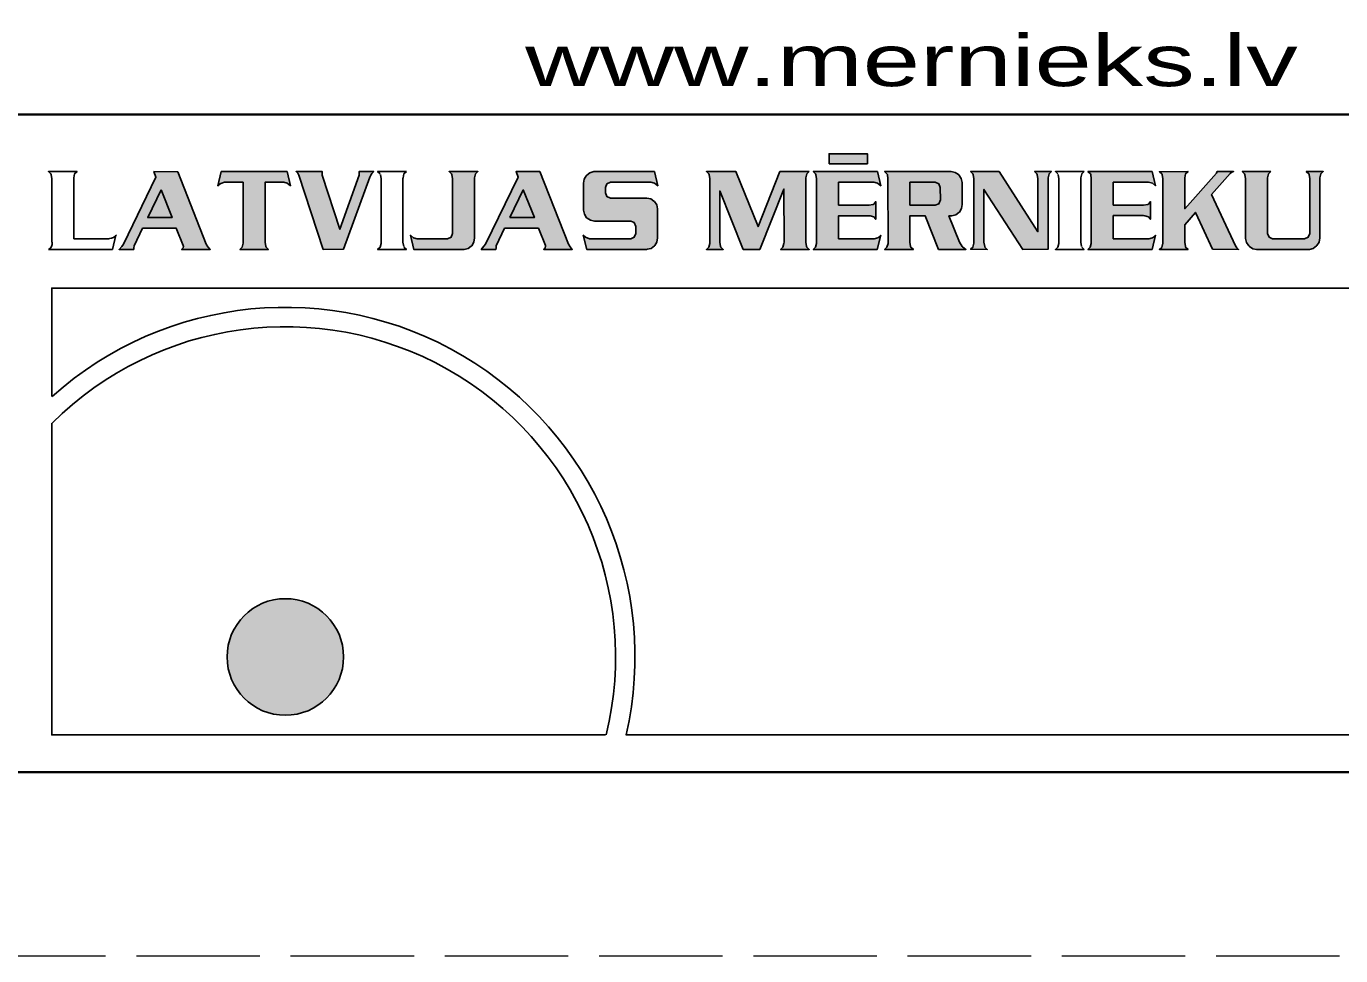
# Model space of a CAD drawing. Extents: x 380758 to 381729, y 283236 to 283533.
# Drawn here: x 381701.8 to 381719.69, y 283235.88 to 283248.53 of the extents above; entities that cross this region are included whole.
import ezdxf

# ---------------------------------------------------------------- set-up
doc = ezdxf.new("R2010")
doc.units = 0
doc.header["$LTSCALE"] = 0.28
doc.linetypes.add('LONG_DASHED', pattern=[7.5, 6, -1.5])
doc.layers.add('63', color=7, linetype='Continuous', lineweight=13)

msp = doc.modelspace()

# ---------------------------------------------------------------- hatches: boundary and pattern name
at = {"layer": '63'}
for points in [[(381712.727, 283246.655), (381713.248, 283246.655), (381713.248, 283246.791), (381712.726, 283246.791)], [(381703.858, 283246.547), (381703.533, 283246.548), (381703.561, 283246.475), (381703.118, 283245.561), (381703.096, 283245.531), (381703.06, 283245.489), (381703.26, 283245.49), (381703.262, 283245.511), (381703.263, 283245.538), (381703.379, 283245.778), (381703.839, 283245.777), (381703.933, 283245.541), (381703.935, 283245.529), (381703.931, 283245.512), (381703.91, 283245.49), (381704.3, 283245.489), (381704.269, 283245.524), (381704.247, 283245.562)], [(381704.749, 283246.403), (381704.749, 283245.586), (381704.749, 283245.573), (381704.735, 283245.518), (381704.704, 283245.49), (381705.093, 283245.49), (381705.061, 283245.518), (381705.057, 283245.528), (381705.048, 283245.586), (381705.047, 283246.403), (381705.301, 283246.403), (381705.047, 283246.403), (381705.301, 283246.403), (381705.348, 283246.389), (381705.392, 283246.355), (381705.346, 283246.548), (381704.45, 283246.549), (381704.404, 283246.355), (381704.435, 283246.381), (381704.446, 283246.388), (381704.497, 283246.403)], [(381705.837, 283245.49), (381706.113, 283245.491), (381706.474, 283246.473), (381706.487, 283246.502), (381706.499, 283246.525), (381706.526, 283246.548), (381706.328, 283246.548), (381706.328, 283246.502), (381706.066, 283245.764), (381705.825, 283246.499), (381705.825, 283246.548), (381705.47, 283246.548), (381705.493, 283246.529), (381705.509, 283246.499)], [(381707.758, 283245.489), (381707.811, 283245.502), (381707.854, 283245.535), (381707.86, 283245.54), (381707.889, 283245.589), (381707.898, 283245.645), (381707.898, 283246.452), (381707.899, 283246.466), (381707.913, 283246.52), (381707.944, 283246.548), (381707.553, 283246.548), (381707.587, 283246.519), (381707.591, 283246.51), (381707.599, 283246.451), (381707.599, 283245.706), (381707.58, 283245.654), (381707.58, 283245.654), (381707.531, 283245.633), (381707.118, 283245.633), (381707.07, 283245.648), (381707.025, 283245.682), (381707.072, 283245.489), (381707.75, 283245.489)], [(381708.788, 283246.549), (381708.464, 283246.549), (381708.491, 283246.475), (381708.049, 283245.561), (381708.026, 283245.532), (381707.99, 283245.489), (381708.191, 283245.489), (381708.192, 283245.511), (381708.195, 283245.538), (381708.309, 283245.777), (381708.769, 283245.777), (381708.864, 283245.541), (381708.866, 283245.529), (381708.861, 283245.512), (381708.841, 283245.489), (381709.23, 283245.489), (381709.2, 283245.524), (381709.177, 283245.562)], [(381710.074, 283245.855), (381710.095, 283245.803), (381710.093, 283245.707), (381710.093, 283245.707), (381710.074, 283245.655), (381710.025, 283245.634), (381709.473, 283245.634), (381709.463, 283245.635), (381709.411, 283245.657), (381709.38, 283245.682), (381709.426, 283245.49), (381710.243, 283245.49), (381710.251, 283245.491), (381710.304, 283245.502), (381710.348, 283245.536), (381710.354, 283245.542), (381710.382, 283245.59), (381710.392, 283245.645), (381710.392, 283246.03), (381710.392, 283246.04), (381710.379, 283246.095), (381710.348, 283246.141), (381710.341, 283246.148), (381710.297, 283246.178), (381710.243, 283246.188), (381709.749, 283246.187), (381709.701, 283246.208), (381709.681, 283246.259), (381709.682, 283246.332), (381709.701, 283246.382), (381709.749, 283246.403), (381710.301, 283246.403), (381710.349, 283246.39), (381710.394, 283246.355), (381710.348, 283246.548), (381709.532, 283246.548), (381709.524, 283246.548), (381709.47, 283246.534), (381709.426, 283246.502), (381709.419, 283246.493), (381709.391, 283246.446), (381709.383, 283246.39), (381709.382, 283246.032), (381709.381, 283246.023), (381709.394, 283245.967), (381709.425, 283245.921), (381709.432, 283245.914), (381709.478, 283245.886), (381709.533, 283245.875), (381710.025, 283245.875)], [(381712.456, 283246.548), (381712.056, 283246.548), (381711.758, 283245.801), (381711.458, 283246.548), (381711.055, 283246.548), (381711.087, 283246.519), (381711.091, 283246.51), (381711.1, 283246.451), (381711.1, 283245.586), (381711.1, 283245.572), (381711.087, 283245.518), (381711.055, 283245.49), (381711.284, 283245.49), (381711.252, 283245.519), (381711.248, 283245.528), (381711.238, 283245.586), (381711.238, 283246.286), (381711.557, 283245.49), (381711.781, 283245.49), (381712.111, 283246.311), (381712.112, 283245.586), (381712.111, 283245.572), (381712.098, 283245.518), (381712.065, 283245.49), (381712.456, 283245.49), (381712.423, 283245.519), (381712.42, 283245.528), (381712.411, 283245.586), (381712.41, 283246.452), (381712.411, 283246.465), (381712.423, 283246.52)], [(381712.556, 283246.452), (381712.556, 283245.586), (381712.556, 283245.572), (381712.543, 283245.518), (381712.51, 283245.49), (381713.382, 283245.49), (381713.429, 283245.682), (381713.402, 283245.658), (381713.388, 283245.649), (381713.338, 283245.634), (381712.855, 283245.634), (381712.855, 283245.948), (381713.269, 283245.948), (381713.283, 283245.947), (381713.334, 283245.934), (381713.36, 283245.899), (381713.36, 283246.14), (381713.334, 283246.106), (381713.325, 283246.101), (381713.269, 283246.091), (381712.855, 283246.092), (381712.856, 283246.403), (381713.337, 283246.403), (381713.387, 283246.389), (381713.43, 283246.355), (381713.383, 283246.548), (381712.51, 283246.549), (381712.543, 283246.519), (381712.547, 283246.51)], [(381713.527, 283246.451), (381713.528, 283245.586), (381713.528, 283245.572), (381713.514, 283245.518), (381713.482, 283245.49), (381713.873, 283245.49), (381713.84, 283245.519), (381713.836, 283245.528), (381713.827, 283245.586), (381713.827, 283245.948), (381714.033, 283245.948), (381714.216, 283245.49), (381714.588, 283245.49), (381714.586, 283245.49), (381714.542, 283245.525), (381714.537, 283245.53), (381714.503, 283245.586), (381714.358, 283245.948), (381714.389, 283245.948), (381714.398, 283245.948), (381714.449, 283245.96), (381714.494, 283245.992), (381714.5, 283245.998), (381714.528, 283246.045), (381714.539, 283246.102), (381714.538, 283246.389), (381714.539, 283246.401), (381714.524, 283246.455), (381714.494, 283246.503), (381714.489, 283246.508), (381714.442, 283246.538), (381714.389, 283246.548), (381713.482, 283246.548), (381713.514, 283246.519), (381713.519, 283246.511)], [(381715.041, 283246.548), (381714.651, 283246.548), (381714.683, 283246.52), (381714.687, 283246.51), (381714.696, 283246.451), (381714.696, 283245.586), (381714.696, 283245.573), (381714.683, 283245.518), (381714.651, 283245.491), (381714.88, 283245.49), (381714.848, 283245.518), (381714.844, 283245.528), (381714.834, 283245.586), (381714.834, 283246.307), (381715.363, 283245.49), (381715.706, 283245.491), (381715.706, 283246.451), (381715.707, 283246.465), (381715.72, 283246.52), (381715.753, 283246.548), (381715.524, 283246.548), (381715.556, 283246.519), (381715.559, 283246.511), (381715.569, 283246.451), (381715.569, 283245.731)], [(381716.295, 283246.451), (381716.295, 283245.586), (381716.294, 283245.572), (381716.282, 283245.518), (381716.25, 283245.49), (381717.122, 283245.49), (381717.168, 283245.682), (381717.141, 283245.658), (381717.128, 283245.649), (381717.077, 283245.634), (381716.595, 283245.634), (381716.595, 283245.949), (381717.008, 283245.949), (381717.022, 283245.948), (381717.073, 283245.933), (381717.1, 283245.899), (381717.1, 283246.14), (381717.073, 283246.106), (381717.063, 283246.101), (381717.008, 283246.092), (381716.595, 283246.092), (381716.595, 283246.403), (381717.076, 283246.404), (381717.127, 283246.389), (381717.169, 283246.355), (381717.122, 283246.549), (381716.25, 283246.548), (381716.283, 283246.519), (381716.287, 283246.51)], [(381717.947, 283245.491), (381718.301, 283245.489), (381718.277, 283245.511), (381718.259, 283245.536), (381717.934, 283246.238), (381718.188, 283246.525), (381718.208, 283246.54), (381718.233, 283246.548), (381718.007, 283246.548), (381718, 283246.526), (381717.567, 283246.044), (381717.567, 283246.452), (381717.568, 283246.466), (381717.58, 283246.52), (381717.613, 283246.549), (381717.223, 283246.547), (381717.255, 283246.519), (381717.259, 283246.51), (381717.268, 283246.451), (381717.268, 283245.587), (381717.268, 283245.573), (381717.255, 283245.517), (381717.223, 283245.49), (381717.613, 283245.49), (381717.58, 283245.519), (381717.576, 283245.528), (381717.568, 283245.586), (381717.568, 283245.826), (381717.715, 283245.993), (381717.72, 283245.981)], [(381718.741, 283246.548), (381718.35, 283246.548), (381718.382, 283246.519), (381718.386, 283246.51), (381718.395, 283246.451), (381718.395, 283245.645), (381718.396, 283245.637), (381718.408, 283245.583), (381718.441, 283245.536), (381718.447, 283245.528), (381718.493, 283245.499), (381718.546, 283245.49), (381719.257, 283245.49), (381719.266, 283245.49), (381719.317, 283245.502), (381719.363, 283245.536), (381719.368, 283245.542), (381719.397, 283245.59), (381719.406, 283245.646), (381719.406, 283246.452), (381719.406, 283246.466), (381719.419, 283246.52), (381719.453, 283246.548), (381719.222, 283246.548), (381719.256, 283246.52), (381719.26, 283246.51), (381719.269, 283246.451), (381719.269, 283245.707), (381719.269, 283245.707), (381719.249, 283245.656), (381719.2, 283245.634), (381718.763, 283245.634), (381718.715, 283245.656), (381718.694, 283245.707), (381718.696, 283246.453), (381718.696, 283246.465), (381718.708, 283246.52)], [(381703.631, 283246.299), (381703.782, 283245.922), (381703.45, 283245.922)], [(381708.381, 283245.923), (381708.562, 283246.299), (381708.713, 283245.922)], [(381714.171, 283246.403), (381714.22, 283246.383), (381714.24, 283246.333), (381714.241, 283246.163), (381714.22, 283246.112), (381714.172, 283246.092), (381713.827, 283246.093), (381713.827, 283246.403)], [(381706.1163, 283239.9415, 1), (381704.5296, 283239.9415, 1)]]:
    msp.add_hatch(color=256, dxfattribs=at).paths.add_polyline_path(points)

# ---------------------------------------------------------------- linework, layer by layer
at = {"layer": '63', "lineweight": 35}
msp.add_line((381701.495, 283247.325), (381726.495, 283247.326), dxfattribs=at)
at = {"layer": '63', "lineweight": 25}
msp.add_line((381702.924, 283245.634), (381702.442, 283245.634), dxfattribs=at)
at = {"layer": '63', "linetype": 'LONG_DASHED'}
msp.add_lwpolyline([(381728.995, 283532.875), (381308.495, 283532.875), (381308.495, 283235.875), (381728.995, 283235.875)], close=True, dxfattribs=at)
at = {"layer": '63'}
msp.add_lwpolyline([(381318.495, 283530.375), (381726.495, 283530.375), (381726.495, 283238.375), (381318.495, 283238.375)], close=True, dxfattribs=at)
at = {"layer": '63', "lineweight": 35}
msp.add_lwpolyline([(381726.495, 283275.876), (381726.495, 283238.375), (381633.995, 283238.375)], dxfattribs=at)
at = {"layer": '63', "lineweight": 25}
for points in [[(381712.727, 283246.655), (381713.248, 283246.655), (381713.248, 283246.791), (381712.726, 283246.791)], [(381703.858, 283246.547), (381703.533, 283246.548), (381703.561, 283246.475), (381703.118, 283245.561), (381703.096, 283245.531), (381703.06, 283245.489), (381703.26, 283245.49), (381703.262, 283245.511), (381703.263, 283245.538), (381703.379, 283245.778), (381703.839, 283245.777), (381703.933, 283245.541), (381703.935, 283245.529), (381703.931, 283245.512), (381703.91, 283245.49), (381704.3, 283245.489), (381704.269, 283245.524), (381704.247, 283245.562)], [(381704.749, 283246.403), (381704.749, 283245.586), (381704.749, 283245.573), (381704.735, 283245.518), (381704.704, 283245.49), (381705.093, 283245.49), (381705.061, 283245.518), (381705.057, 283245.528), (381705.048, 283245.586), (381705.047, 283246.403), (381705.301, 283246.403), (381705.047, 283246.403), (381705.301, 283246.403), (381705.348, 283246.389), (381705.392, 283246.355), (381705.346, 283246.548), (381704.45, 283246.549), (381704.404, 283246.355), (381704.435, 283246.381), (381704.446, 283246.388), (381704.497, 283246.403)], [(381705.837, 283245.49), (381706.113, 283245.491), (381706.474, 283246.473), (381706.487, 283246.502), (381706.499, 283246.525), (381706.526, 283246.548), (381706.328, 283246.548), (381706.328, 283246.502), (381706.066, 283245.764), (381705.825, 283246.499), (381705.825, 283246.548), (381705.47, 283246.548), (381705.493, 283246.529), (381705.509, 283246.499)], [(381707.758, 283245.489), (381707.811, 283245.502), (381707.854, 283245.535), (381707.86, 283245.54), (381707.889, 283245.589), (381707.898, 283245.645), (381707.898, 283246.452), (381707.899, 283246.466), (381707.913, 283246.52), (381707.944, 283246.548), (381707.553, 283246.548), (381707.587, 283246.519), (381707.591, 283246.51), (381707.599, 283246.451), (381707.599, 283245.706), (381707.58, 283245.654), (381707.58, 283245.654), (381707.531, 283245.633), (381707.118, 283245.633), (381707.07, 283245.648), (381707.025, 283245.682), (381707.072, 283245.489), (381707.75, 283245.489)], [(381708.788, 283246.549), (381708.464, 283246.549), (381708.491, 283246.475), (381708.049, 283245.561), (381708.026, 283245.532), (381707.99, 283245.489), (381708.191, 283245.489), (381708.192, 283245.511), (381708.195, 283245.538), (381708.309, 283245.777), (381708.769, 283245.777), (381708.864, 283245.541), (381708.866, 283245.529), (381708.861, 283245.512), (381708.841, 283245.489), (381709.23, 283245.489), (381709.2, 283245.524), (381709.177, 283245.562)], [(381710.074, 283245.855), (381710.095, 283245.803), (381710.093, 283245.707), (381710.093, 283245.707), (381710.074, 283245.655), (381710.025, 283245.634), (381709.473, 283245.634), (381709.463, 283245.635), (381709.411, 283245.657), (381709.38, 283245.682), (381709.426, 283245.49), (381710.243, 283245.49), (381710.251, 283245.491), (381710.304, 283245.502), (381710.348, 283245.536), (381710.354, 283245.542), (381710.382, 283245.59), (381710.392, 283245.645), (381710.392, 283246.03), (381710.392, 283246.04), (381710.379, 283246.095), (381710.348, 283246.141), (381710.341, 283246.148), (381710.297, 283246.178), (381710.243, 283246.188), (381709.749, 283246.187), (381709.701, 283246.208), (381709.681, 283246.259), (381709.682, 283246.332), (381709.701, 283246.382), (381709.749, 283246.403), (381710.301, 283246.403), (381710.349, 283246.39), (381710.394, 283246.355), (381710.348, 283246.548), (381709.532, 283246.548), (381709.524, 283246.548), (381709.47, 283246.534), (381709.426, 283246.502), (381709.419, 283246.493), (381709.391, 283246.446), (381709.383, 283246.39), (381709.382, 283246.032), (381709.381, 283246.023), (381709.394, 283245.967), (381709.425, 283245.921), (381709.432, 283245.914), (381709.478, 283245.886), (381709.533, 283245.875), (381710.025, 283245.875)], [(381712.456, 283246.548), (381712.056, 283246.548), (381711.758, 283245.801), (381711.458, 283246.548), (381711.055, 283246.548), (381711.087, 283246.519), (381711.091, 283246.51), (381711.1, 283246.451), (381711.1, 283245.586), (381711.1, 283245.572), (381711.087, 283245.518), (381711.055, 283245.49), (381711.284, 283245.49), (381711.252, 283245.519), (381711.248, 283245.528), (381711.238, 283245.586), (381711.238, 283246.286), (381711.557, 283245.49), (381711.781, 283245.49), (381712.111, 283246.311), (381712.112, 283245.586), (381712.111, 283245.572), (381712.098, 283245.518), (381712.065, 283245.49), (381712.456, 283245.49), (381712.423, 283245.519), (381712.42, 283245.528), (381712.411, 283245.586), (381712.41, 283246.452), (381712.411, 283246.465), (381712.423, 283246.52)], [(381712.556, 283246.452), (381712.556, 283245.586), (381712.556, 283245.572), (381712.543, 283245.518), (381712.51, 283245.49), (381713.382, 283245.49), (381713.429, 283245.682), (381713.402, 283245.658), (381713.388, 283245.649), (381713.338, 283245.634), (381712.855, 283245.634), (381712.855, 283245.948), (381713.269, 283245.948), (381713.283, 283245.947), (381713.334, 283245.934), (381713.36, 283245.899), (381713.36, 283246.14), (381713.334, 283246.106), (381713.325, 283246.101), (381713.269, 283246.091), (381712.855, 283246.092), (381712.856, 283246.403), (381713.337, 283246.403), (381713.387, 283246.389), (381713.43, 283246.355), (381713.383, 283246.548), (381712.51, 283246.549), (381712.543, 283246.519), (381712.547, 283246.51)], [(381713.527, 283246.451), (381713.528, 283245.586), (381713.528, 283245.572), (381713.514, 283245.518), (381713.482, 283245.49), (381713.873, 283245.49), (381713.84, 283245.519), (381713.836, 283245.528), (381713.827, 283245.586), (381713.827, 283245.948), (381714.033, 283245.948), (381714.216, 283245.49), (381714.588, 283245.49), (381714.586, 283245.49), (381714.542, 283245.525), (381714.537, 283245.53), (381714.503, 283245.586), (381714.358, 283245.948), (381714.389, 283245.948), (381714.398, 283245.948), (381714.449, 283245.96), (381714.494, 283245.992), (381714.5, 283245.998), (381714.528, 283246.045), (381714.539, 283246.102), (381714.538, 283246.389), (381714.539, 283246.401), (381714.524, 283246.455), (381714.494, 283246.503), (381714.489, 283246.508), (381714.442, 283246.538), (381714.389, 283246.548), (381713.482, 283246.548), (381713.514, 283246.519), (381713.519, 283246.511)], [(381715.041, 283246.548), (381714.651, 283246.548), (381714.683, 283246.52), (381714.687, 283246.51), (381714.696, 283246.451), (381714.696, 283245.586), (381714.696, 283245.573), (381714.683, 283245.518), (381714.651, 283245.491), (381714.88, 283245.49), (381714.848, 283245.518), (381714.844, 283245.528), (381714.834, 283245.586), (381714.834, 283246.307), (381715.363, 283245.49), (381715.706, 283245.491), (381715.706, 283246.451), (381715.707, 283246.465), (381715.72, 283246.52), (381715.753, 283246.548), (381715.524, 283246.548), (381715.556, 283246.519), (381715.559, 283246.511), (381715.569, 283246.451), (381715.569, 283245.731)], [(381716.295, 283246.451), (381716.295, 283245.586), (381716.294, 283245.572), (381716.282, 283245.518), (381716.25, 283245.49), (381717.122, 283245.49), (381717.168, 283245.682), (381717.141, 283245.658), (381717.128, 283245.649), (381717.077, 283245.634), (381716.595, 283245.634), (381716.595, 283245.949), (381717.008, 283245.949), (381717.022, 283245.948), (381717.073, 283245.933), (381717.1, 283245.899), (381717.1, 283246.14), (381717.073, 283246.106), (381717.063, 283246.101), (381717.008, 283246.092), (381716.595, 283246.092), (381716.595, 283246.403), (381717.076, 283246.404), (381717.127, 283246.389), (381717.169, 283246.355), (381717.122, 283246.549), (381716.25, 283246.548), (381716.283, 283246.519), (381716.287, 283246.51)], [(381717.947, 283245.491), (381718.301, 283245.489), (381718.277, 283245.511), (381718.259, 283245.536), (381717.934, 283246.238), (381718.188, 283246.525), (381718.208, 283246.54), (381718.233, 283246.548), (381718.007, 283246.548), (381718, 283246.526), (381717.567, 283246.044), (381717.567, 283246.452), (381717.568, 283246.466), (381717.58, 283246.52), (381717.613, 283246.549), (381717.223, 283246.547), (381717.255, 283246.519), (381717.259, 283246.51), (381717.268, 283246.451), (381717.268, 283245.587), (381717.268, 283245.573), (381717.255, 283245.517), (381717.223, 283245.49), (381717.613, 283245.49), (381717.58, 283245.519), (381717.576, 283245.528), (381717.568, 283245.586), (381717.568, 283245.826), (381717.715, 283245.993), (381717.72, 283245.981)], [(381718.741, 283246.548), (381718.35, 283246.548), (381718.382, 283246.519), (381718.386, 283246.51), (381718.395, 283246.451), (381718.395, 283245.645), (381718.396, 283245.637), (381718.408, 283245.583), (381718.441, 283245.536), (381718.447, 283245.528), (381718.493, 283245.499), (381718.546, 283245.49), (381719.257, 283245.49), (381719.266, 283245.49), (381719.317, 283245.502), (381719.363, 283245.536), (381719.368, 283245.542), (381719.397, 283245.59), (381719.406, 283245.646), (381719.406, 283246.452), (381719.406, 283246.466), (381719.419, 283246.52), (381719.453, 283246.548), (381719.222, 283246.548), (381719.256, 283246.52), (381719.26, 283246.51), (381719.269, 283246.451), (381719.269, 283245.707), (381719.269, 283245.707), (381719.249, 283245.656), (381719.2, 283245.634), (381718.763, 283245.634), (381718.715, 283245.656), (381718.694, 283245.707), (381718.696, 283246.453), (381718.696, 283246.465), (381718.708, 283246.52)], [(381703.631, 283246.299), (381703.782, 283245.922), (381703.45, 283245.922)], [(381708.381, 283245.923), (381708.562, 283246.299), (381708.713, 283245.922)], [(381714.171, 283246.403), (381714.22, 283246.383), (381714.24, 283246.333), (381714.241, 283246.163), (381714.22, 283246.112), (381714.172, 283246.092), (381713.827, 283246.093), (381713.827, 283246.403)]]:
    msp.add_lwpolyline(points, close=True, dxfattribs=at)
for points in [[(381702.442, 283245.634), (381702.442, 283246.452), (381702.443, 283246.465), (381702.455, 283246.52), (381702.488, 283246.548), (381702.098, 283246.548), (381702.131, 283246.519), (381702.134, 283246.511), (381702.143, 283246.451), (381702.143, 283245.586)], [(381706.971, 283246.548), (381706.58, 283246.548), (381706.613, 283246.519)], [(381706.617, 283246.51), (381706.627, 283246.451), (381706.626, 283245.586)], [(381706.935, 283245.528), (381706.925, 283245.586), (381706.925, 283246.453), (381706.926, 283246.465), (381706.938, 283246.52), (381706.971, 283246.548)], [(381716.199, 283246.548), (381715.808, 283246.548), (381715.84, 283246.519)], [(381715.843, 283246.51), (381715.853, 283246.451), (381715.853, 283245.586)], [(381716.161, 283245.528), (381716.152, 283245.586), (381716.152, 283246.452), (381716.153, 283246.465), (381716.165, 283246.52), (381716.199, 283246.548)], [(381702.097, 283245.49), (381702.97, 283245.49), (381703.017, 283245.682)], [(381706.626, 283245.586), (381706.626, 283245.572), (381706.613, 283245.518), (381706.58, 283245.49), (381706.971, 283245.49), (381706.938, 283245.519)], [(381715.853, 283245.586), (381715.852, 283245.572), (381715.84, 283245.519), (381715.807, 283245.49), (381716.198, 283245.49), (381716.165, 283245.519)], [(381702.144, 283243.485), (381702.143, 283244.963), (381725.944, 283244.962), (381725.943, 283238.88), (381709.957, 283238.88)], [(381702.143, 283243.123), (381702.143, 283238.88), (381709.684, 283238.88)]]:
    msp.add_lwpolyline(points, dxfattribs=at)
msp.add_circle((381705.323, 283239.9415), 0.7933, dxfattribs=at)
for centre, radius, start, end in [((381702.0414, 283245.5695), 0.1059, 321.06729, 353.70902), ((381701.8137, 283245.6051), 0.3364, 351.93332, 357.36424), ((381702.9224, 283245.7661), 0.1283, 273.84044, 321.44716), ((381702.103, 283245.523), 0.029, 271.4811, 316.10505), ((381705.323, 283239.9415), 4.76, 347.16012, 131.81002), ((381705.323, 283239.9415), 4.4956, 346.39075, 134.90058)]:
    msp.add_arc(centre, radius, start, end, dxfattribs=at)

# ---------------------------------------------------------------- texts
at = {"layer": '63', "width": 1.5}
msp.add_text('www.mernieks.lv', height=0.699, dxfattribs=at).set_placement((381708.589, 283247.712))

doc.saveas('drawing.dxf')
